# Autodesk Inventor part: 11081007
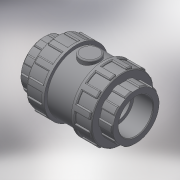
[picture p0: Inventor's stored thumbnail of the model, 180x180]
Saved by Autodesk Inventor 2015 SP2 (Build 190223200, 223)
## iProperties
Created: 2017-11
Part Number: 11081007
Material: Generic
Description: PLASSON CHECK VALVE THR 3/4" PTFE COATED SPRING + EPDM O-RING
Document SubType Name: Modeling
Designer: KIM
Density: 1 g/cm^3
Appearance: Default
Author: KIM
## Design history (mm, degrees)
derived "110810 - 110610 110910 - 110010.ipt"
feature "Solid1::110810 - 110610 110910 - 110010.ipt"
tag "TaggingFeature1"
body "Solid1"
other parameters: "d0" = 89, "d1" = 24.117, "d2" = 55, "d3" = 19, "d4" = 19.2936, "d5" = 13.3, "d7" = 33.7638, "d8" = 49.5, "d13" = 0.72351, "d23" = 19, "d24" = 52.8, "d25" = 0.48234, "d26" = 0.72351, "d27" = 8.25, "d28" = 4.125, "d29" = 14.25, "d30" = 0, "d35" = 0.72351, "d39" = 27.5, "d45" = 360 deg, "d47" = 0.48234, "d50" = 27.5, "d51" = 16.5, "d53" = 0, "d54" = 1.1, "d55" = 4.8234, "d56" = 2.4117, "d58" = 0, "d59" = 0.72351, "d61" = 360 deg, "G_" = 24.117, "l_" = 19, "H_" = 89, "K_" = 55
